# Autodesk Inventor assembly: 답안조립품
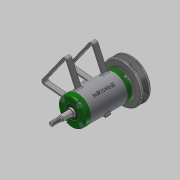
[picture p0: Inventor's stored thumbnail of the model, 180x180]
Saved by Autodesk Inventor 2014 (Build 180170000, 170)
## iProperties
Created: 2016-03
Part Number: 답안조립품
Document SubType Name: Assembly
Designer: SCD-A15
Author: SCD-A15
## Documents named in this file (12)
- C:\Users\SCD-A15\Desktop\460307v1001\답안조립품.iam
- C:\Users\SCD-A15\Desktop\460307v1001\1.본체.ipt
- C:\Users\SCD-A15\Desktop\460307v1001\베어링 15 x 32 x 9.ipt
- C:\Users\SCD-A15\Desktop\460307v1001\커버.ipt
- C:\Users\SCD-A15\Desktop\460307v1001\오일 실 15 25 7.ipt
- C:\Users\SCD-A15\Desktop\460307v1001\볼트 M4 x 12.ipt
- C:\Users\SCD-A15\Desktop\460307v1001\V벨트풀리.ipt
- C:\Users\SCD-A15\Desktop\460307v1001\축.ipt
- C:\Users\SCD-A15\Desktop\460307v1001\키 3 x 3 x 12.ipt
- C:\Users\SCD-A15\Desktop\460307v1001\와셔 8x17.ipt
- C:\Users\SCD-A15\Desktop\460307v1001\스프링와셔 8.ipt
- C:\Users\SCD-A15\Desktop\460307v1001\너트 M 8.ipt
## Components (12 placed, 4 different names)
1. 1.본체:1
2. KS B 2023 6002 - 15 x 32 x 9:1
3. KS B 2023 6002 - 15 x 32 x 9:2
4. V벨트풀리:1 — 각도:2
5. ISO 4762 M4 x 12:1
6. ISO 4762 M4 x 12:2
7. ISO 4762 M4 x 12:3
8. ISO 4762 M4 x 12:4
9. ISO 4762 M4 x 12:5
10. ISO 4762 M4 x 12:6
11. ISO 4762 M4 x 12:7
12. ISO 4762 M4 x 12:8
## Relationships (1: Angle 1)
- 각도:2 [Angle]: V벨트풀리:1
